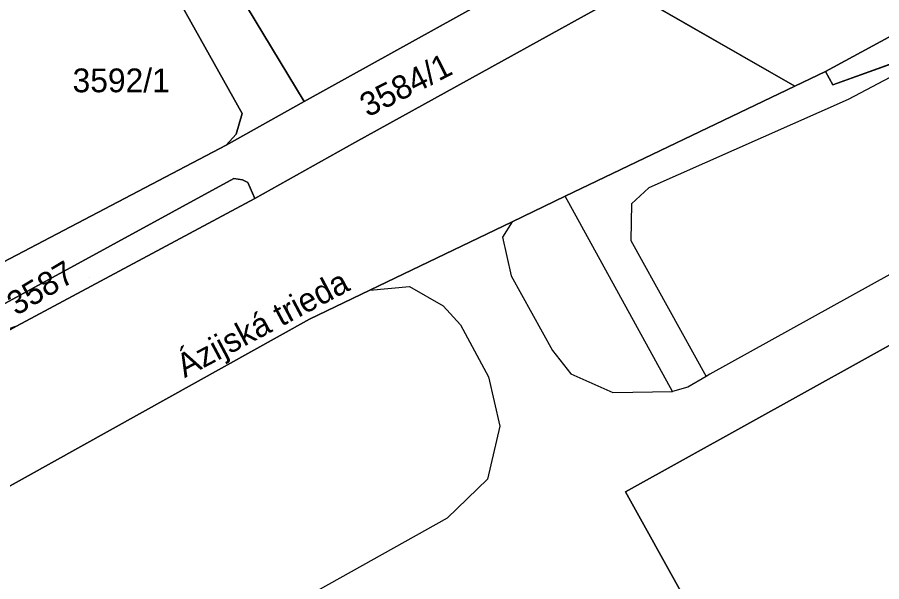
# Model space of a CAD drawing. Extents: x -262715 to -259381, y -1237238 to -1231182.
# Drawn here: x -261646.8 to -261574, y -1236208.9 to -1236161.4 of the extents above; entities that cross this region are included whole.
import ezdxf

# ---------------------------------------------------------------- set-up
doc = ezdxf.new("R2010")
doc.units = 0
for name, color, linetype in [('body_kn', 7, 'Continuous'), ('kladpar_druhypozemkov', 7, 'Continuous'), ('kladpar_hranice', 7, 'Continuous'), ('kladpar_parcelnecisla', 7, 'Continuous'), ('kladpar_plochy', 7, 'Continuous'), ('popisy', 7, 'Continuous'), ('zappar_hrandruhpozemk', 7, 'Continuous')]:
    doc.layers.add(name, color=color, linetype=linetype)

msp = doc.modelspace()

# ---------------------------------------------------------------- linework, layer by layer
at = {"layer": 'body_kn'}
for p, q in [((-261578.77, -1236165.97), (-261578.77, -1236165.97)), ((-261581.36, -1236167.21), (-261581.36, -1236167.21)), ((-261581.36, -1236167.21), (-261581.36, -1236167.21)), ((-261578.16, -1236167.1), (-261578.16, -1236167.1)), ((-261576.86, -1236168.32), (-261576.86, -1236168.32)), ((-261622.66, -1236168.51), (-261622.66, -1236168.51)), ((-261627.88, -1236169.5), (-261627.88, -1236169.5)), ((-261628.39, -1236171.24), (-261628.39, -1236171.24)), ((-261618.4, -1236171.96), (-261618.4, -1236171.96)), ((-261629.23, -1236172.16), (-261629.23, -1236172.16)), ((-261628.56, -1236174.99), (-261628.56, -1236174.99)), ((-261627.84, -1236175.09), (-261627.84, -1236175.09)), ((-261627.4, -1236175.32), (-261627.4, -1236175.32)), ((-261593.64, -1236175.77), (-261593.64, -1236175.77)), ((-261626.81, -1236176.66), (-261626.81, -1236176.66)), ((-261626.81, -1236176.66), (-261626.81, -1236176.66)), ((-261600.67, -1236176.48), (-261600.67, -1236176.48)), ((-261595.09, -1236177.11), (-261595.09, -1236177.11)), ((-261605.15, -1236178.63), (-261605.15, -1236178.63)), ((-261605.15, -1236178.63), (-261605.15, -1236178.63)), ((-261605.97, -1236179.91), (-261605.97, -1236179.91)), ((-261595.16, -1236180.19), (-261595.16, -1236180.19)), ((-261605.22, -1236183.18), (-261605.22, -1236183.18)), ((-261617.12, -1236184.38), (-261617.12, -1236184.38)), ((-261617.12, -1236184.38), (-261617.12, -1236184.38)), ((-261613.8, -1236184.06), (-261613.8, -1236184.06)), ((-261610.94, -1236185.7), (-261610.94, -1236185.7)), ((-261622.19, -1236186.81), (-261622.19, -1236186.81)), ((-261609.5, -1236187.3), (-261609.5, -1236187.3)), ((-261601.74, -1236189.45), (-261601.74, -1236189.45)), ((-261600.21, -1236191.41), (-261600.21, -1236191.41)), ((-261588.81, -1236191.64), (-261588.81, -1236191.64)), ((-261588.52, -1236191.46), (-261588.52, -1236191.46)), ((-261607.13, -1236191.67), (-261607.13, -1236191.67)), ((-261596.67, -1236192.99), (-261596.67, -1236192.99)), ((-261591.66, -1236192.92), (-261591.66, -1236192.92)), ((-261591.66, -1236192.92), (-261591.66, -1236192.92)), ((-261590.35, -1236192.55), (-261590.35, -1236192.55)), ((-261606.18, -1236195.82), (-261606.18, -1236195.82)), ((-261607.22, -1236200.29), (-261607.22, -1236200.29)), ((-261595.6, -1236201.36), (-261595.6, -1236201.36)), ((-261610.61, -1236203.57), (-261610.61, -1236203.57))]:
    msp.add_line(p, q, dxfattribs=at)
at = {"layer": 'kladpar_druhypozemkov'}
for p, q in [((-261637.46, -1236165.89), (-261637.46, -1236165.89)), ((-261613.49, -1236166.14), (-261613.49, -1236166.14)), ((-261640.7, -1236183.29), (-261640.7, -1236183.29))]:
    msp.add_line(p, q, dxfattribs=at)
at = {"layer": 'kladpar_hranice'}
for p, q in [((-261581.36, -1236167.21), (-261595.33, -1236159.18)), ((-261595.33, -1236159.18), (-261581.36, -1236167.21))]:
    msp.add_line(p, q, dxfattribs=at)
for points in [[(-261483.14, -1236094.58), (-261485.64, -1236097.66), (-261486.61, -1236098.69), (-261493.42, -1236105.89), (-261496.71, -1236109.37), (-261504.88, -1236118.01), (-261537.1, -1236142.13), (-261544.2, -1236147.19), (-261578.77, -1236165.97), (-261581.36, -1236167.21)], [(-261643.83, -1236131.3), (-261642.07, -1236134.41), (-261636.12, -1236145.29), (-261633.61, -1236149.62), (-261628.14, -1236159.38), (-261622.66, -1236168.51), (-261629.23, -1236172.16), (-261628.39, -1236171.24), (-261627.88, -1236169.5), (-261647.79, -1236133.89)], [(-261600.52, -1236156.2), (-261622.66, -1236168.51), (-261628.14, -1236159.38), (-261633.61, -1236149.62), (-261636.12, -1236145.29), (-261642.07, -1236134.41), (-261642.49, -1236132.07)], [(-261647.79, -1236133.89), (-261627.88, -1236169.5), (-261628.39, -1236171.24), (-261629.23, -1236172.16), (-261653.15, -1236184.71), (-261654.42, -1236185.37), (-261655, -1236185.37), (-261656.06, -1236185.36), (-261657.41, -1236184.77), (-261658.53, -1236183.77), (-261662.57, -1236178.13), (-261665.01, -1236173.78)], [(-261537.1, -1236142.13), (-261536.16, -1236143.09), (-261544.5, -1236150.84), (-261566.66, -1236162.95), (-261578.16, -1236167.1), (-261578.77, -1236165.97), (-261544.2, -1236147.19), (-261537.1, -1236142.13)], [(-261660.15, -1236187.2), (-261655, -1236185.37), (-261654.42, -1236185.37), (-261653.15, -1236184.71), (-261629.23, -1236172.16), (-261622.66, -1236168.51), (-261600.52, -1236156.2)], [(-261678.54, -1236205.12), (-261669.86, -1236200.27), (-261646.86, -1236187.4), (-261626.81, -1236176.66), (-261618.4, -1236171.96), (-261595.33, -1236159.18)], [(-261595.33, -1236159.18), (-261618.4, -1236171.96), (-261626.81, -1236176.66), (-261627.4, -1236175.32), (-261627.84, -1236175.09), (-261628.56, -1236174.99), (-261654.54, -1236189.14), (-261657.99, -1236188.59), (-261660.15, -1236187.2)], [(-261590.66, -1236210.25), (-261595.6, -1236201.36), (-261525.64, -1236162.51)], [(-261525.64, -1236162.51), (-261595.6, -1236201.36), (-261590.66, -1236210.25)], [(-261665.42, -1236210.86), (-261622.19, -1236186.81), (-261617.12, -1236184.38), (-261605.15, -1236178.63), (-261600.67, -1236176.48), (-261581.36, -1236167.21), (-261578.77, -1236165.97), (-261578.16, -1236167.1), (-261566.66, -1236162.95)], [(-261581.36, -1236167.21), (-261600.67, -1236176.48), (-261605.15, -1236178.63), (-261617.12, -1236184.38), (-261622.19, -1236186.81), (-261665.42, -1236210.86), (-261667.59, -1236212.07), (-261675.95, -1236216.71), (-261682.18, -1236220.45), (-261686.6, -1236223.78)], [(-261626.81, -1236176.66), (-261646.86, -1236187.4), (-261650.06, -1236188.51), (-261654.54, -1236189.14), (-261628.56, -1236174.99), (-261627.84, -1236175.09), (-261627.4, -1236175.32), (-261626.81, -1236176.66)]]:
    msp.add_lwpolyline(points, dxfattribs=at)
at = {"layer": 'kladpar_plochy'}
for p, q in [((-261525.64, -1236162.51), (-261595.6, -1236201.36)), ((-261578.16, -1236167.1), (-261566.66, -1236162.95)), ((-261581.36, -1236167.21), (-261578.77, -1236165.97)), ((-261578.77, -1236165.97), (-261578.16, -1236167.1)), ((-261600.67, -1236176.48), (-261581.36, -1236167.21)), ((-261605.15, -1236178.63), (-261600.67, -1236176.48)), ((-261617.12, -1236184.38), (-261605.15, -1236178.63)), ((-261622.19, -1236186.81), (-261617.12, -1236184.38)), ((-261665.42, -1236210.86), (-261622.19, -1236186.81)), ((-261595.6, -1236201.36), (-261590.66, -1236210.25))]:
    msp.add_line(p, q, dxfattribs=at)
for points in [[(-261595.33, -1236159.18), (-261589.42, -1236155.91), (-261584.61, -1236153.71), (-261557.17, -1236141.66), (-261548.65, -1236136.72), (-261529.6, -1236125.36), (-261526.87, -1236123.93), (-261518.63, -1236118.9), (-261509.93, -1236111.81), (-261490.99, -1236092.81), (-261489.43, -1236090.9), (-261483.14, -1236094.58), (-261485.64, -1236097.66), (-261486.61, -1236098.69), (-261493.42, -1236105.89), (-261496.71, -1236109.37), (-261504.88, -1236118.01), (-261537.1, -1236142.13), (-261544.2, -1236147.19), (-261578.77, -1236165.97), (-261581.36, -1236167.21)], [(-261643.83, -1236131.3), (-261642.07, -1236134.41), (-261636.12, -1236145.29), (-261633.61, -1236149.62), (-261628.14, -1236159.38), (-261622.66, -1236168.51), (-261629.23, -1236172.16), (-261628.39, -1236171.24), (-261627.88, -1236169.5), (-261647.79, -1236133.89), (-261646.82, -1236131.65), (-261650.1, -1236129.75), (-261651.78, -1236126.74)], [(-261642.49, -1236132.07), (-261640.1, -1236133.44), (-261630.06, -1236139.22), (-261633.32, -1236141.01), (-261629.53, -1236147.68), (-261625.92, -1236145.32), (-261623.73, -1236144.07), (-261618.95, -1236151.3), (-261616.89, -1236154.72), (-261610, -1236150.75), (-261600.52, -1236156.2), (-261622.66, -1236168.51), (-261628.14, -1236159.38), (-261633.61, -1236149.62), (-261636.12, -1236145.29), (-261642.07, -1236134.41)], [(-261662.43, -1236167.81), (-261660.09, -1236167.83), (-261660.08, -1236166.62), (-261654.56, -1236166.69), (-261654.57, -1236167.89), (-261648.59, -1236167.96), (-261648.5, -1236160.68), (-261647.31, -1236160.69), (-261647.19, -1236150.38), (-261648.38, -1236150.37), (-261648.29, -1236143.08), (-261651.74, -1236143.04), (-261647.79, -1236133.89), (-261627.88, -1236169.5), (-261628.39, -1236171.24), (-261629.23, -1236172.16), (-261653.15, -1236184.71), (-261654.42, -1236185.37), (-261655, -1236185.37), (-261656.06, -1236185.36), (-261657.41, -1236184.77), (-261658.53, -1236183.77), (-261662.57, -1236178.13), (-261665.01, -1236173.78)], [(-261537.1, -1236142.13), (-261536.16, -1236143.09), (-261544.5, -1236150.84), (-261566.66, -1236162.95), (-261578.16, -1236167.1), (-261578.77, -1236165.97), (-261544.2, -1236147.19)], [(-261660.15, -1236187.2), (-261655, -1236185.37), (-261654.42, -1236185.37), (-261653.15, -1236184.71), (-261629.23, -1236172.16), (-261622.66, -1236168.51), (-261600.52, -1236156.2), (-261595.33, -1236159.18), (-261618.4, -1236171.96), (-261626.81, -1236176.66), (-261627.4, -1236175.32), (-261627.84, -1236175.09), (-261628.56, -1236174.99), (-261654.54, -1236189.14), (-261657.99, -1236188.59)], [(-261678.54, -1236205.12), (-261669.86, -1236200.27), (-261646.86, -1236187.4), (-261626.81, -1236176.66), (-261618.4, -1236171.96), (-261595.33, -1236159.18), (-261581.36, -1236167.21), (-261600.67, -1236176.48), (-261605.15, -1236178.63), (-261617.12, -1236184.38), (-261622.19, -1236186.81), (-261665.42, -1236210.86), (-261667.59, -1236212.07), (-261675.95, -1236216.71), (-261682.18, -1236220.45), (-261686.6, -1236223.78)], [(-261626.81, -1236176.66), (-261646.86, -1236187.4), (-261650.06, -1236188.51), (-261654.54, -1236189.14), (-261628.56, -1236174.99), (-261627.84, -1236175.09), (-261627.4, -1236175.32)]]:
    msp.add_lwpolyline(points, close=True, dxfattribs=at)
msp.add_lwpolyline([(-261590.66, -1236210.25), (-261595.6, -1236201.36), (-261525.64, -1236162.51)], dxfattribs=at)
at = {"layer": 'zappar_hrandruhpozemk'}
for p, q in [((-261566.66, -1236162.95), (-261576.86, -1236168.32)), ((-261576.86, -1236168.32), (-261593.64, -1236175.77)), ((-261591.66, -1236192.92), (-261600.67, -1236176.48)), ((-261605.22, -1236183.18), (-261601.74, -1236189.45)), ((-261609.5, -1236187.3), (-261607.13, -1236191.67)), ((-261610.61, -1236203.57), (-261624.6, -1236211.38))]:
    msp.add_line(p, q, dxfattribs=at)
for points in [[(-261547.78, -1236168.9), (-261588.52, -1236191.46), (-261588.81, -1236191.64)], [(-261593.64, -1236175.77), (-261595.09, -1236177.11), (-261595.16, -1236180.19), (-261588.81, -1236191.64), (-261590.35, -1236192.55), (-261591.66, -1236192.92)], [(-261605.15, -1236178.63), (-261605.97, -1236179.91), (-261605.22, -1236183.18)], [(-261617.12, -1236184.38), (-261613.8, -1236184.06), (-261610.94, -1236185.7), (-261609.5, -1236187.3)], [(-261601.74, -1236189.45), (-261600.21, -1236191.41), (-261596.67, -1236192.99), (-261591.66, -1236192.92)], [(-261607.13, -1236191.67), (-261606.18, -1236195.82), (-261607.22, -1236200.29), (-261610.61, -1236203.57)]]:
    msp.add_lwpolyline(points, dxfattribs=at)

# ---------------------------------------------------------------- texts
at = {"layer": 'kladpar_parcelnecisla'}
for s, rotation, p in [('3584/1', 27, (-261617.301, -1236169.853)), ('3587', 31, (-261646.882, -1236186.572))]:
    msp.add_text(s, height=2, rotation=rotation, dxfattribs=at).set_placement(p)
msp.add_text('3592/1', height=2, dxfattribs=at).set_placement((-261642.145, -1236167.72))
at = {"layer": 'popisy'}
msp.add_text('Ázijská trieda', height=2, rotation=28, dxfattribs=at).set_placement((-261632.713, -1236191.798))

doc.saveas('drawing.dxf')
